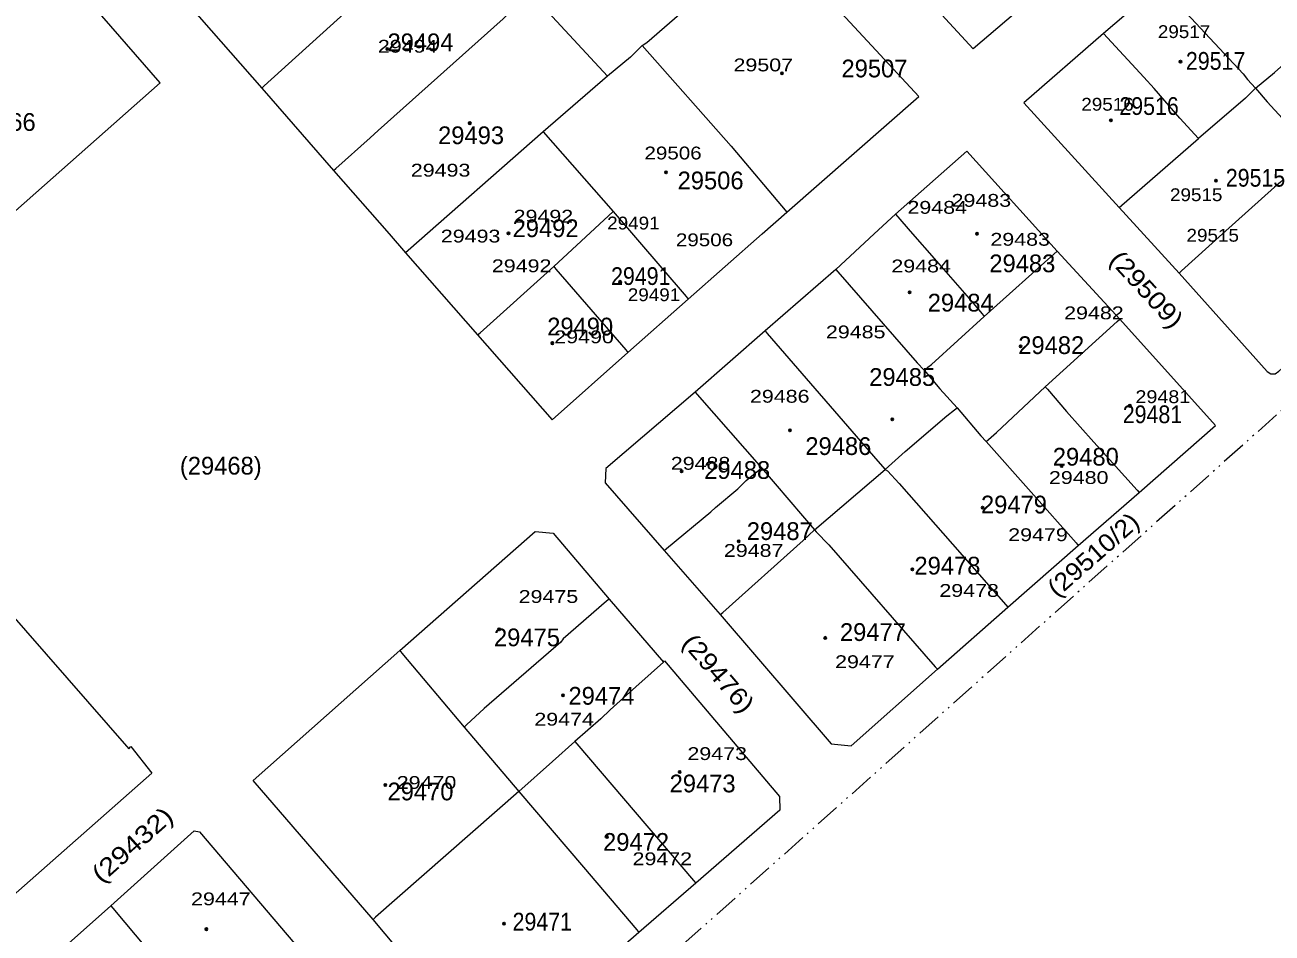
# Model space of a CAD drawing. Extents: x 650553 to 652508, y 239277 to 241647.
# Drawn here: x 651434 to 651687, y 240108.2 to 240292.4 of the extents above; entities that cross this region are included whole.
import ezdxf

# ---------------------------------------------------------------- set-up
doc = ezdxf.new("R2010")
doc.units = 0
doc.header["$PDMODE"] = 32
doc.header["$PDSIZE"] = 0.5
doc.linetypes.add('DASH_DOUBLE_DOT', pattern=[9.2, 5, -1.2, 0.3, -1.2, 0.3, -1.2])
for name, color, linetype in [('19', 7, 'Continuous'), ('20', 7, 'Continuous'), ('6', 7, 'Continuous')]:
    doc.layers.add(name, color=color, linetype=linetype)
for name, color, linetype, lineweight in [('3', 7, 'Continuous', 13), ('5', 7, 'Continuous', 13), ('52', 7, 'DASH_DOUBLE_DOT', 13)]:
    doc.layers.add(name, color=color, linetype=linetype, lineweight=lineweight)

msp = doc.modelspace()

# ---------------------------------------------------------------- linework, layer by layer
at = {"layer": '3'}
for p, q in [((651583.56, 240250), (651588.54, 240254.39)), ((651610.62, 240253.99), (651606.31, 240250)), ((651655.99, 240255.37), (651668.16, 240242.04)), ((651480.3, 240139.14), (651510.03, 240165.47))]:
    msp.add_line(p, q, dxfattribs=at)
for points in [[(651426.69, 240250), (651461.4, 240280.6), (651417.67, 240330.87), (651412.21, 240325.69), (651412.52, 240325.19), (651382.18, 240294.85)], [(651441.12, 240326.31), (651452.95, 240312.7), (651467.4, 240296.27), (651482.03, 240279.58), (651496.59, 240262.84), (651507.85, 240250)], [(651588.54, 240254.39), (651615.36, 240277.83), (651584.84, 240310.76)], [(651675.65, 240310.46), (651664.33, 240300.5), (651652.85, 240290.65)], [(651646.39, 240304.66), (651626.38, 240287.53), (651608.88, 240306.57)], [(651652.85, 240290.65), (651636.66, 240276.58), (651655.99, 240255.37)], [(651643.42, 240246.51), (651625.11, 240266.77), (651610.62, 240253.99)], [(651507.85, 240250), (651511.21, 240246.17), (651525.82, 240229.49), (651540.98, 240212.31), (651556.33, 240225.95), (651568.55, 240236.77), (651583.56, 240250)], [(651606.31, 240250), (651598.5, 240242.78), (651584.14, 240230.3), (651569.94, 240217.91)], [(651668.16, 240242.04), (651686.05, 240222.11), (651686.75, 240221.63), (651687.63, 240221.63), (651688.38, 240222.12), (651707.38, 240239.01), (651719.59, 240250)], [(651660.07, 240197.54), (651675.57, 240211.13), (651656.11, 240232.69), (651643.42, 240246.51)], [(651569.94, 240217.91), (651551.85, 240202.42), (651551.68, 240199.52), (651563.67, 240185.8), (651575.07, 240172.78)], [(651601.65, 240146.14), (651619.13, 240161.7), (651633.43, 240174.26), (651647.71, 240186.8), (651660.07, 240197.54)], [(651510.03, 240165.47), (651537.49, 240189.62), (651541.14, 240189.29), (651552.49, 240175.92), (651563.53, 240163.11)], [(651429.87, 240174.36), (651455.086, 240145.538), (651455.493, 240146.045), (651459.75, 240140.58)], [(651575.07, 240172.78), (651597.59, 240146.54), (651601.65, 240146.14)], [(651563.53, 240163.11), (651563.77, 240163.41), (651587.06, 240135.89), (651587.13, 240133.12), (651570.08, 240118.31), (651558.55, 240108.32)], [(651459.75, 240140.58), (651399.97, 240087.93), (651395.8, 240092.84), (651396.15, 240093.24), (651375, 240117.7)], [(651558.55, 240108.32), (651529.89, 240083.28), (651527.6, 240083.46), (651504.61, 240110.95), (651480.3, 240139.14)], [(651451.4, 240113.72), (651468.29, 240128.9), (651469.42, 240128.69), (651489.89, 240104.65)], [(651409.9, 240077.1), (651431.81, 240096.29), (651451.4, 240113.72)]]:
    msp.add_lwpolyline(points, dxfattribs=at)
at = {"layer": '5'}
for p, q in [((651539.13, 240270.7), (651553.32, 240254.56)), ((651610.62, 240253.99), (651614.08, 240250))]:
    msp.add_line(p, q, dxfattribs=at)
for points in [[(651482.03, 240279.58), (651482.53, 240280.033), (651514.23, 240308.76), (651515.61, 240310.04), (651517.9, 240312.16)], [(651559.24, 240288.17), (651560.13, 240288.82), (651568.32, 240295.9), (651584.84, 240310.76)], [(651664.33, 240300.5), (651664.795, 240300), (651681.13, 240282.45), (651682.03, 240281.32), (651683.68, 240279.53), (651681.62, 240277.52), (651672.09, 240269.35)], [(651496.59, 240262.84), (651497.09, 240263.287), (651504.01, 240269.47), (651505.67, 240270.97), (651531.04, 240293.58), (651532.9, 240295.45), (651536.69, 240298.72), (651552.21, 240281.98)], [(651655.99, 240255.37), (651672.09, 240269.35), (651668.29, 240273.48), (651663.07, 240279.51), (651660.97, 240281.75), (651652.85, 240290.65)], [(651683.68, 240279.53), (651687.51, 240282.73), (651694.89, 240289.25)], [(651559.24, 240288.17), (651556.84, 240285.82), (651555.27, 240284.55), (651552.21, 240281.98), (651539.13, 240270.7)], [(651559.24, 240288.17), (651577.27, 240267.81), (651588.54, 240254.39)], [(651683.68, 240279.53), (651686.05, 240276.8), (651695.36, 240266.66)], [(651539.13, 240270.7), (651511.71, 240246.609), (651511.21, 240246.17)], [(651689.41, 240261.12), (651688.7, 240260.49), (651687.5, 240259.47), (651676.99, 240250)], [(651525.82, 240229.49), (651526.32, 240229.939), (651541.27, 240243.35), (651553.32, 240254.56)], [(651553.32, 240254.56), (651568.122, 240237.27), (651568.55, 240236.77)], [(651614.08, 240250), (651618.43, 240244.99), (651626.01, 240236.35), (651628.191, 240233.75), (651628.61, 240233.25)], [(651668.16, 240242.04), (651668.66, 240242.491), (651676.99, 240250)], [(651616.45, 240222.32), (651616.95, 240222.739), (651617.19, 240222.94), (651617.89, 240223.53), (651628.61, 240233.25), (651643.42, 240246.51)], [(651541.27, 240243.35), (651541.703, 240242.85), (651555.897, 240226.45), (651556.33, 240225.95)], [(651598.5, 240242.78), (651598.934, 240242.28), (651614.98, 240223.81), (651616.45, 240222.32)], [(651641.01, 240219), (651655.61, 240232.237), (651656.11, 240232.69)], [(651584.14, 240230.3), (651584.574, 240229.8), (651607.04, 240203.91), (651608.53, 240202.23)], [(651616.45, 240222.32), (651619.64, 240218.55), (651623.1, 240214.68)], [(651629.01, 240207.9), (651629.51, 240208.32), (651631.14, 240209.69), (651641.01, 240219)], [(651641.01, 240219), (651641.439, 240218.5), (651645.32, 240213.98), (651650.89, 240207.76), (651651.51, 240207.01), (651659.618, 240198.04), (651660.07, 240197.54)], [(651569.94, 240217.91), (651570.377, 240217.41), (651583.4, 240202.51)], [(651608.53, 240202.23), (651612.61, 240205.85), (651621.02, 240213.06), (651622.6, 240214.291), (651623.1, 240214.68)], [(651623.1, 240214.68), (651627.95, 240209), (651629.01, 240207.9)], [(651629.01, 240207.9), (651647.267, 240187.3), (651647.71, 240186.8)], [(651563.67, 240185.8), (651564.17, 240186.213), (651573.15, 240193.63), (651574.11, 240194.47), (651578.62, 240198.31), (651580.35, 240199.94), (651582.9, 240202.089), (651583.4, 240202.51)], [(651575.07, 240172.78), (651575.57, 240173.226), (651591.9, 240187.8), (651594.17, 240189.96), (651608.53, 240202.23)], [(651583.4, 240202.51), (651591.76, 240192.79), (651594.17, 240189.96)], [(651608.53, 240202.23), (651608.99, 240201.96), (651611.37, 240199.35), (651632.99, 240174.76), (651633.43, 240174.26)], [(651594.17, 240189.96), (651594.52, 240189.56), (651597.07, 240186.95), (651618.693, 240162.2), (651619.13, 240161.7)], [(651552.49, 240175.92), (651551.99, 240175.485), (651543.2, 240167.83), (651542.69, 240167.21), (651527.19, 240153.75), (651523.58, 240150.421), (651523.08, 240149.96)], [(651510.03, 240165.47), (651510.451, 240164.97), (651523.08, 240149.96), (651534.21, 240136.91)], [(651563.53, 240163.11), (651555.42, 240155.86), (651552.75, 240153.48), (651550.81, 240151.66), (651545.55, 240147.03)], [(651545.55, 240147.03), (651541.01, 240143), (651534.21, 240136.91)], [(651545.55, 240147.03), (651545.977, 240146.53), (651569.653, 240118.81), (651570.08, 240118.31)], [(651534.21, 240136.91), (651505.11, 240111.389), (651504.61, 240110.95)], [(651534.21, 240136.91), (651547.31, 240121.56), (651558.126, 240108.82), (651558.55, 240108.32)], [(651451.4, 240113.72), (651451.818, 240113.22), (651470.25, 240091.16), (651470.65, 240090.63), (651471.695, 240089.53), (651472.17, 240089.03)]]:
    msp.add_lwpolyline(points, dxfattribs=at)
at = {"layer": '52'}
msp.add_lwpolyline([(651750.052, 240268.782), (651729.12, 240250.009), (651567.141, 240105.534), (651448.015, 239999.895)], dxfattribs=at)
at = {"layer": '6'}
for p in [(651507.494, 240287.5), (651668.45, 240284.925), (651587.578, 240282.575), (651524.239, 240272.445), (651654.318, 240273.01), (651564.06, 240262.47), (651675.629, 240260.785), (651532.099, 240250.095), (651627.164, 240250.01), (651554.758, 240240.255), (651613.472, 240238.155), (651540.994, 240227.83), (651636.001, 240227.205), (651658.159, 240215.115), (651609.957, 240212.367), (651589.191, 240210.13), (651644.333, 240202.9), (651567.22, 240201.855), (651628.287, 240194.47), (651578.815, 240187.645), (651614.04, 240181.965), (651530.196, 240169.79), (651596.356, 240168.05), (651543.15, 240156.415), (651566.837, 240140.86), (651507.102, 240138.21), (651552.086, 240127.675), (651531.184, 240110.095), (651470.795, 240108.965)]:
    msp.add_point(p, dxfattribs=at)

# ---------------------------------------------------------------- texts
at = {"layer": '19'}
for s, p in [('29494', (651507.548, 240287.049)), ('29507', (651599.657, 240281.738)), ('29466', (651422.773, 240270.885)), ('29493', (651517.808, 240268.19)), ('29506', (651566.406, 240259.03)), ('29492', (651532.927, 240249.332)), ('29483', (651629.656, 240242.209)), ('29484', (651617.16, 240234.244)), ('29490', (651539.946, 240229.395)), ('29482', (651635.52, 240225.623)), ('29485', (651605.282, 240219.157)), ('29486', (651592.323, 240205.148)), ('29480', (651642.538, 240202.993)), ('(29468)', (651465.422, 240201.174)), ('29488', (651571.804, 240200.298)), ('29479', (651627.96, 240193.294)), ('29487', (651580.444, 240187.905)), ('29478', (651614.461, 240180.901)), ('29477', (651599.342, 240167.43)), ('29475', (651529.147, 240166.352)), ('29474', (651544.265, 240154.498)), ('29473', (651564.784, 240136.717)), ('29470', (651507.547, 240135.1)), ('29472', (651551.285, 240124.863))]:
    msp.add_text(s, height=3.6, dxfattribs=at).set_placement(p)
at = {"layer": '19', "width": 0.9}
for s, p in [('29517', (651669.54, 240283.278)), ('29516', (651656.041, 240274.118)), ('29515', (651677.639, 240259.569)), ('29491', (651552.906, 240239.633)), ('29481', (651656.732, 240211.602)), ('29471', (651532.926, 240108.698))]:
    msp.add_text(s, height=3.6, dxfattribs=at).set_placement(p)
at = {"layer": '19'}
for s, rotation, width, p in [('(29509)', 312.559, 1.15, (651653.79, 240244.542)), ('(29510/2)', 41.288, 1.1, (651643.41, 240176.108)), ('(29476)', 310.756, 1.15, (651567.11, 240166.917)), ('(29432)', 41.661, 1.2, (651449.512, 240118.133))]:
    msp.add_text(s, height=3.6, rotation=rotation, dxfattribs=dict(at, width=width)).set_placement(p)
at = {"layer": '20'}
for s, width, p in [('29517', 1.1, (651663.848, 240289.711)), ('29494', 1.25, (651505.587, 240286.745)), ('29507', 1.25, (651577.746, 240282.958)), ('29516', 1.1, (651648.318, 240274.98)), ('29506', 1.2, (651559.679, 240265.095)), ('29493', 1.25, (651512.279, 240261.611)), ('29515', 1.1, (651666.311, 240256.631)), ('29484', 1.25, (651613.038, 240254.069)), ('29483', 1.25, (651621.994, 240255.486)), ('29492', 1.25, (651533.131, 240252.275)), ('29491', 1.1, (651552.121, 240250.888)), ('29515', 1.1, (651669.665, 240248.409)), ('29493', 1.25, (651518.366, 240248.247)), ('29506', 1.2, (651566.067, 240247.483)), ('29483', 1.25, (651629.871, 240247.592)), ('29492', 1.25, (651528.719, 240242.22)), ('29484', 1.25, (651609.777, 240242.183)), ('29491', 1.1, (651556.303, 240236.348)), ('29482', 1.25, (651644.833, 240232.667)), ('29485', 1.25, (651596.495, 240228.807)), ('29490', 1.25, (651541.388, 240227.813)), ('29486', 1.25, (651581.083, 240215.751)), ('29481', 1.15, (651659.306, 240215.668)), ('29488', 1.25, (651565.028, 240202.153)), ('29480', 1.25, (651641.746, 240199.267)), ('29479', 1.25, (651633.489, 240187.677)), ('29487', 1.25, (651575.793, 240184.485)), ('29475', 1.25, (651534.155, 240175.139)), ('29478', 1.25, (651619.514, 240176.374)), ('29477', 1.25, (651598.358, 240161.918)), ('29474', 1.25, (651537.339, 240150.252)), ('29473', 1.25, (651568.395, 240143.276)), ('29470', 1.25, (651509.422, 240137.425)), ('29472', 1.25, (651557.263, 240121.95)), ('29447', 1.25, (651467.687, 240113.817))]:
    msp.add_text(s, height=2.6, dxfattribs=dict(at, width=width)).set_placement(p)

doc.saveas('drawing.dxf')
